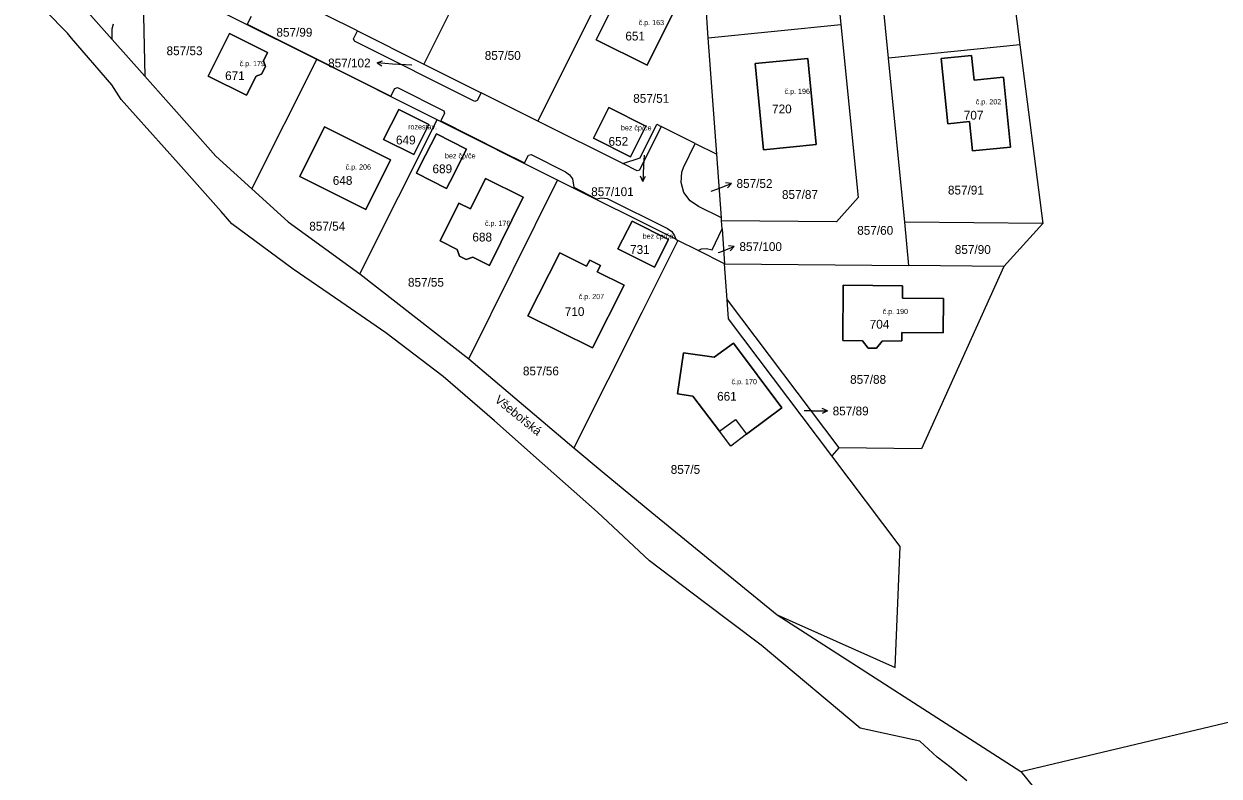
# Model space of a CAD drawing. Extents: x -887272 to -880188, y -1026687 to -1021896.
# Drawn here: x -886371.5 to -886140.7, y -1024532.4 to -1024387 of the extents above; entities that cross this region are included whole.
import ezdxf

# ---------------------------------------------------------------- set-up
doc = ezdxf.new("R2010")
doc.units = 0
for name, color, linetype in [('Definiční body', 7, 'Continuous'), ('Hranice parcel', 7, 'Continuous'), ('Parcelní čísla', 7, 'Continuous'), ('Polygon budovy', 7, 'Continuous'), ('Pop  PČ popisy', 7, 'Continuous'), ('Vnitřní kresba', 7, 'Continuous')]:
    doc.layers.add(name, color=color, linetype=linetype)

msp = doc.modelspace()

# ---------------------------------------------------------------- linework, layer by layer
at = {"layer": 'Hranice parcel'}
for p, q in [((-886183.54, -1024356.31), (-886179.13, -1024391.05)), ((-886204.52, -1024393.61), (-886207.95, -1024358.74)), ((-886278.64, -1024363.46), (-886294.28, -1024394.77)), ((-886272.23, -1024405.8), (-886256.6, -1024374.49)), ((-886365.01, -1024378.17), (-886354.46, -1024390.01)), ((-886307.08, -1024388.36), (-886319.32, -1024382.23)), ((-886239.34, -1024389.68), (-886239.83, -1024382.88)), ((-886307.08, -1024388.36), (-886294.28, -1024394.77)), ((-886239.34, -1024389.68), (-886213.7, -1024387.12)), ((-886354.51, -1024398.78), (-886362.33, -1024389.78)), ((-886354.46, -1024390.01), (-886348.15, -1024397.1)), ((-886237.7, -1024412.2), (-886239.34, -1024389.68)), ((-886179.13, -1024391.05), (-886204.52, -1024393.61)), ((-886179.13, -1024391.05), (-886174.74, -1024425.59)), ((-886327.47, -1024418.9), (-886314.97, -1024393.92)), ((-886291.71, -1024405.57), (-886314.97, -1024393.92)), ((-886294.28, -1024394.77), (-886283.2, -1024400.31)), ((-886201.39, -1024425.35), (-886204.52, -1024393.61)), ((-886352.76, -1024401.6), (-886354.51, -1024398.78)), ((-886341.64, -1024413.97), (-886352.76, -1024401.6)), ((-886272.23, -1024405.8), (-886283.2, -1024400.31)), ((-886306.62, -1024435.3), (-886291.71, -1024405.57)), ((-886268.45, -1024417.21), (-886291.71, -1024405.57)), ((-886255.82, -1024414.02), (-886272.23, -1024405.8)), ((-886241.84, -1024410.12), (-886248.41, -1024406.82)), ((-886241.84, -1024410.12), (-886237.7, -1024412.2)), ((-886236.81, -1024424.51), (-886237.7, -1024412.2)), ((-886333.44, -1024423.24), (-886341.64, -1024413.97)), ((-886285.57, -1024451.74), (-886268.45, -1024417.21)), ((-886245.62, -1024428.63), (-886268.45, -1024417.21)), ((-886236.77, -1024425.07), (-886236.81, -1024424.51)), ((-886236.66, -1024426.62), (-886236.77, -1024425.07)), ((-886174.74, -1024425.59), (-886201.39, -1024425.35)), ((-886200.57, -1024433.71), (-886201.39, -1024425.35)), ((-886236.66, -1024426.62), (-886236.17, -1024433.37)), ((-886174.74, -1024425.59), (-886182.28, -1024433.89)), ((-886245.62, -1024428.63), (-886245.19, -1024428.85)), ((-886241.27, -1024430.81), (-886245.19, -1024428.85)), ((-886236.17, -1024433.37), (-886241.27, -1024430.81)), ((-886310.31, -1024440.75), (-886319.49, -1024434.41)), ((-886235.67, -1024440.34), (-886236.17, -1024433.37)), ((-886236.17, -1024433.37), (-886200.57, -1024433.71)), ((-886182.28, -1024433.89), (-886200.57, -1024433.71)), ((-886306.62, -1024435.3), (-886285.57, -1024451.74)), ((-886301.62, -1024446.68), (-886310.31, -1024440.75)), ((-886235.67, -1024440.34), (-886214.13, -1024468.94)), ((-886290.56, -1024455.12), (-886301.62, -1024446.68)), ((-886285.57, -1024451.74), (-886265.29, -1024468.92)), ((-886280.6, -1024463.7), (-886290.56, -1024455.12)), ((-886271.41, -1024471.88), (-886280.6, -1024463.7)), ((-886214.13, -1024468.94), (-886215.5, -1024470.45)), ((-886260.72, -1024481.38), (-886271.41, -1024471.88)), ((-886250.66, -1024490.78), (-886260.72, -1024481.38)), ((-886240.32, -1024498.62), (-886250.66, -1024490.78)), ((-886229.14, -1024507.06), (-886240.32, -1024498.62)), ((-886226, -1024501.2), (-886178.96, -1024531.47)), ((-886210, -1024523.12), (-886229.14, -1024507.06)), ((-886198.48, -1024525.62), (-886210, -1024523.12)), ((-886195.1, -1024528.68), (-886198.48, -1024525.62)), ((-886178.96, -1024531.47), (-886171.88, -1024540.22))]:
    msp.add_line(p, q, dxfattribs=at)
for points in [[(-886217.52, -1024348.31), (-886217.13, -1024352.27), (-886213.7, -1024387.12)], [(-886314.97, -1024393.92), (-886345.74, -1024378.52), (-886348.57, -1024379.62), (-886348.15, -1024397.1)], [(-886245.34, -1024383.36), (-886251.15, -1024395.02), (-886261.02, -1024390.1), (-886255.2, -1024378.44), (-886245.34, -1024383.36)], [(-886362.33, -1024389.78), (-886363.1, -1024388.82), (-886371.52, -1024380.16)], [(-886327.64, -1024385.57), (-886328.39, -1024387.07), (-886322.23, -1024390.15), (-886300.63, -1024401), (-886299.85, -1024399.51), (-886299.39, -1024399.33), (-886290.43, -1024403.82), (-886290.28, -1024404.26), (-886290.97, -1024405.73), (-886279.3, -1024411.67), (-886274.8, -1024413.85), (-886274.06, -1024412.4), (-886273.57, -1024412.25), (-886266.94, -1024415.62), (-886266.14, -1024416.17), (-886265.55, -1024416.98), (-886265.28, -1024418.59), (-886260.98, -1024420.8), (-886259.88, -1024420.61), (-886258.89, -1024420.73), (-886247.21, -1024426.55), (-886246.38, -1024427.12), (-886245.86, -1024427.94), (-886245.62, -1024428.63)], [(-886354.46, -1024390.01), (-886354.46, -1024387.95), (-886354.24, -1024386.98)], [(-886283.2, -1024400.31), (-886283.98, -1024401.84), (-886284.42, -1024402.02), (-886307.69, -1024390.37), (-886307.85, -1024389.88), (-886307.08, -1024388.36)], [(-886213.7, -1024387.12), (-886210.41, -1024420.59), (-886214.57, -1024425.25), (-886236.77, -1024425.07)], [(-886178.96, -1024531.47), (-886032.7, -1024496.7), (-886031.92, -1024386.7)], [(-886325.62, -1024396.76), (-886326.69, -1024397.12), (-886328.55, -1024400.8), (-886335.92, -1024397.12), (-886331.8, -1024388.85), (-886324.44, -1024392.55), (-886325.24, -1024394.18), (-886324.86, -1024395.25), (-886325.62, -1024396.76)], [(-886188.48, -1024393.13), (-886187.97, -1024397.86), (-886182.34, -1024397.28), (-886180.95, -1024410.81), (-886188.27, -1024411.57), (-886188.86, -1024405.87), (-886193.06, -1024406.31), (-886194.38, -1024393.73), (-886188.48, -1024393.13)], [(-886230.26, -1024394.68), (-886220.11, -1024393.69), (-886218.47, -1024410.35), (-886228.67, -1024411.35), (-886230.26, -1024394.68)], [(-886348.15, -1024397.1), (-886334.48, -1024412.57), (-886327.47, -1024418.9)], [(-886302.04, -1024409.36), (-886299.13, -1024403.55), (-886293.32, -1024406.45), (-886296.23, -1024412.27), (-886302.04, -1024409.36)], [(-886258.53, -1024403.18), (-886251.39, -1024406.78), (-886254.36, -1024412.68), (-886261.5, -1024409.08), (-886258.53, -1024403.18)], [(-886305.48, -1024422.86), (-886318.23, -1024416.48), (-886313.43, -1024406.91), (-886300.69, -1024413.25), (-886305.48, -1024422.86)], [(-886255.82, -1024414.02), (-886252.48, -1024412.9), (-886249.24, -1024406.4), (-886248.41, -1024406.82)], [(-886248.41, -1024406.82), (-886252.64, -1024415.27), (-886253.07, -1024415.4), (-886255.82, -1024414.02)], [(-886291.85, -1024408.26), (-886286.04, -1024411.21), (-886289.21, -1024417.46), (-886289.88, -1024418.79), (-886295.7, -1024415.85), (-886295.02, -1024414.51), (-886291.85, -1024408.26)], [(-886236.81, -1024424.51), (-886241.25, -1024422.3), (-886242.85, -1024421.18), (-886244.05, -1024419.58), (-886244.6, -1024417.67), (-886244.46, -1024415.68), (-886244.14, -1024414.74), (-886241.84, -1024410.12)], [(-886286.12, -1024432.51), (-886287.41, -1024431.9), (-886287.86, -1024430.59), (-886291.1, -1024428.96), (-886287.5, -1024421.63), (-886285.26, -1024422.72), (-886282.38, -1024416.88), (-886275.06, -1024420.48), (-886281.56, -1024433.68), (-886284.8, -1024432.1), (-886286.12, -1024432.51)], [(-886327.47, -1024418.9), (-886320.47, -1024425.23), (-886306.62, -1024435.3)], [(-886319.49, -1024434.41), (-886331.34, -1024425.62), (-886333.44, -1024423.24)], [(-886249.73, -1024434), (-886256.79, -1024430.45), (-886254.06, -1024425.1), (-886247.03, -1024428.65), (-886249.73, -1024434)], [(-886241.27, -1024430.81), (-886240.65, -1024430.49), (-886239.67, -1024430.42), (-886238.6, -1024430.69), (-886236.66, -1024426.62)], [(-886245.19, -1024428.85), (-886247.91, -1024434.28), (-886252.17, -1024442.77), (-886265.29, -1024468.92)], [(-886262.87, -1024433.84), (-886262.24, -1024432.66), (-886260.17, -1024433.7), (-886260.77, -1024434.89), (-886255.59, -1024437.49), (-886261.69, -1024449.63), (-886274.16, -1024443.45), (-886268.03, -1024431.24), (-886262.87, -1024433.84)], [(-886182.28, -1024433.89), (-886198.12, -1024469.1), (-886214.13, -1024468.94)], [(-886205.74, -1024448.29), (-886206.87, -1024449.68), (-886208.47, -1024449.67), (-886209.52, -1024448.25), (-886213.35, -1024448.19), (-886213.25, -1024437.52), (-886201.83, -1024437.62), (-886201.85, -1024440), (-886193.9, -1024440.07), (-886193.94, -1024446.73), (-886201.92, -1024446.64), (-886201.92, -1024448.28), (-886205.74, -1024448.29)], [(-886215.5, -1024470.45), (-886235.4, -1024444), (-886235.67, -1024440.34)], [(-886242.31, -1024458.96), (-886245.27, -1024458.48), (-886244.14, -1024450.56), (-886238.17, -1024451.42), (-886234.47, -1024448.68), (-886225.11, -1024461.18), (-886231.94, -1024466.32), (-886235.01, -1024468.63), (-886237.19, -1024465.74), (-886242.31, -1024458.96)], [(-886265.29, -1024468.92), (-886259.85, -1024473.53), (-886250.22, -1024481.41), (-886226, -1024501.2)], [(-886226, -1024501.2), (-886203.23, -1024511.39), (-886202.3, -1024488), (-886215.5, -1024470.45)], [(-886189.42, -1024533.25), (-886192.4, -1024530.76), (-886195.1, -1024528.68)]]:
    msp.add_lwpolyline(points, dxfattribs=at)
at = {"layer": 'Polygon budovy'}
for points in [[(-886255.2, -1024378.44), (-886261.02, -1024390.1), (-886251.15, -1024395.02), (-886245.34, -1024383.36)], [(-886331.8, -1024388.85), (-886335.92, -1024397.12), (-886328.55, -1024400.8), (-886326.69, -1024397.12), (-886325.62, -1024396.76), (-886324.86, -1024395.25), (-886325.24, -1024394.18), (-886324.44, -1024392.55)], [(-886188.48, -1024393.13), (-886194.38, -1024393.73), (-886193.06, -1024406.31), (-886188.86, -1024405.87), (-886188.27, -1024411.57), (-886180.95, -1024410.81), (-886182.34, -1024397.28), (-886187.97, -1024397.86)], [(-886230.26, -1024394.68), (-886228.67, -1024411.35), (-886218.47, -1024410.35), (-886220.11, -1024393.69)], [(-886299.13, -1024403.55), (-886302.04, -1024409.36), (-886296.23, -1024412.27), (-886293.32, -1024406.45)], [(-886258.53, -1024403.18), (-886261.5, -1024409.08), (-886254.36, -1024412.68), (-886251.39, -1024406.78)], [(-886300.69, -1024413.25), (-886313.43, -1024406.91), (-886318.23, -1024416.48), (-886305.48, -1024422.86)], [(-886289.21, -1024417.46), (-886286.04, -1024411.21), (-886291.85, -1024408.26), (-886295.02, -1024414.51), (-886295.7, -1024415.85), (-886289.88, -1024418.79)], [(-886282.38, -1024416.88), (-886285.26, -1024422.72), (-886287.5, -1024421.63), (-886291.1, -1024428.96), (-886287.86, -1024430.59), (-886287.41, -1024431.9), (-886286.12, -1024432.51), (-886284.8, -1024432.1), (-886281.56, -1024433.68), (-886275.06, -1024420.48)], [(-886247.03, -1024428.65), (-886254.06, -1024425.1), (-886256.79, -1024430.45), (-886249.73, -1024434)], [(-886274.16, -1024443.45), (-886261.69, -1024449.63), (-886255.59, -1024437.49), (-886260.77, -1024434.89), (-886260.17, -1024433.7), (-886262.24, -1024432.66), (-886262.87, -1024433.84), (-886268.03, -1024431.24)], [(-886213.25, -1024437.52), (-886213.35, -1024448.19), (-886209.52, -1024448.25), (-886208.47, -1024449.67), (-886206.87, -1024449.68), (-886205.74, -1024448.29), (-886201.92, -1024448.28), (-886201.92, -1024446.64), (-886193.94, -1024446.73), (-886193.9, -1024440.07), (-886201.85, -1024440), (-886201.83, -1024437.62)], [(-886237.19, -1024465.74), (-886234.1, -1024463.43), (-886231.94, -1024466.32), (-886225.11, -1024461.18), (-886234.47, -1024448.68), (-886238.17, -1024451.42), (-886244.14, -1024450.56), (-886245.27, -1024458.48), (-886242.31, -1024458.96)]]:
    msp.add_lwpolyline(points, close=True, dxfattribs=at)
at = {"layer": 'Pop  PČ popisy'}
for p, q in [((-886303.32, -1024394.56), (-886302.29, -1024394.13)), ((-886300.33, -1024394.77), (-886303.32, -1024394.56)), ((-886303.32, -1024394.56), (-886302.36, -1024395.13)), ((-886296.59, -1024395.01), (-886300.33, -1024394.77)), ((-886251.73, -1024412.38), (-886251.82, -1024414.44)), ((-886251.82, -1024414.44), (-886251.98, -1024417.44)), ((-886251.98, -1024417.44), (-886252.43, -1024416.41)), ((-886251.98, -1024417.44), (-886251.43, -1024416.46)), ((-886237.68, -1024418.93), (-886234.88, -1024417.85)), ((-886234.88, -1024417.85), (-886235.99, -1024417.75)), ((-886234.88, -1024417.85), (-886235.63, -1024418.68)), ((-886238.79, -1024419.36), (-886237.68, -1024418.93)), ((-886237.13, -1024431.1), (-886234.33, -1024430.03)), ((-886234.33, -1024430.03), (-886235.44, -1024429.92)), ((-886234.33, -1024430.03), (-886235.08, -1024430.85)), ((-886237.41, -1024431.21), (-886237.13, -1024431.1)), ((-886219.31, -1024461.81), (-886220.79, -1024461.81)), ((-886219.31, -1024461.81), (-886216.31, -1024461.81)), ((-886216.31, -1024461.81), (-886217.31, -1024461.31)), ((-886216.31, -1024461.81), (-886217.31, -1024462.31))]:
    msp.add_line(p, q, dxfattribs=at)
at = {"layer": 'Vnitřní kresba'}
for p, q in [((-886237.19, -1024465.74), (-886234.1, -1024463.43)), ((-886234.1, -1024463.43), (-886231.94, -1024466.32))]:
    msp.add_line(p, q, dxfattribs=at)

# ---------------------------------------------------------------- texts
at = {"layer": 'Definiční body'}
for s, p in [('č.p. 163', (-886252.79, -1024387.25)), ('č.p. 179', (-886329.87, -1024395.18)), ('č.p. 196', (-886224.61, -1024400.54)), ('č.p. 202', (-886187.67, -1024402.56)), ('rozestav.', (-886297.31, -1024407.4)), ('bez čp/če', (-886256.21, -1024407.59)), ('bez čp/če', (-886290.19, -1024413)), ('č.p. 206', (-886309.39, -1024415.16)), ('č.p. 176', (-886282.47, -1024426.04)), ('bez čp/če', (-886252.01, -1024428.53)), ('č.p. 207', (-886264.36, -1024440.19)), ('č.p. 190', (-886205.66, -1024443.08)), ('č.p. 170', (-886234.85, -1024456.64))]:
    msp.add_text(s, height=1, dxfattribs=at).set_placement(p)
at = {"layer": 'Parcelní čísla'}
for s, p in [('857/99', (-886322.75, -1024389.49)), ('651', (-886255.35, -1024390.22)), ('857/53', (-886343.97, -1024393.06)), ('857/50', (-886282.51, -1024393.96)), ('857/102', (-886312.77, -1024395.42)), ('671', (-886332.66, -1024397.87)), ('857/51', (-886253.83, -1024402.26)), ('720', (-886227.02, -1024404.3)), ('707', (-886189.98, -1024405.51)), ('649', (-886299.66, -1024410.3)), ('652', (-886258.6, -1024410.56)), ('689', (-886292.6, -1024415.87)), ('648', (-886311.86, -1024418.11)), ('857/101', (-886261.95, -1024420.29)), ('857/52', (-886233.88, -1024418.71)), ('857/91', (-886193.05, -1024419.98)), ('857/87', (-886225.1, -1024420.84)), ('857/54', (-886316.4, -1024426.96)), ('688', (-886284.9, -1024429.06)), ('857/60', (-886210.57, -1024427.76)), ('731', (-886254.44, -1024431.45)), ('857/100', (-886233.32, -1024430.9)), ('857/90', (-886191.72, -1024431.46)), ('857/55', (-886297.34, -1024437.79)), ('710', (-886267.05, -1024443.46)), ('704', (-886208.16, -1024445.9)), ('857/56', (-886275.14, -1024454.93)), ('857/88', (-886211.94, -1024456.56)), ('661', (-886237.63, -1024459.82)), ('857/89', (-886215.31, -1024462.66)), ('857/5', (-886246.59, -1024473.96))]:
    msp.add_text(s, height=1.7, dxfattribs=at).set_placement(p)
at = {"layer": 'Pop  PČ popisy'}
msp.add_text('Všebořská', height=1.7, rotation=321, dxfattribs=at).set_placement((-886280.72, -1024459.91))

doc.saveas('drawing.dxf')
